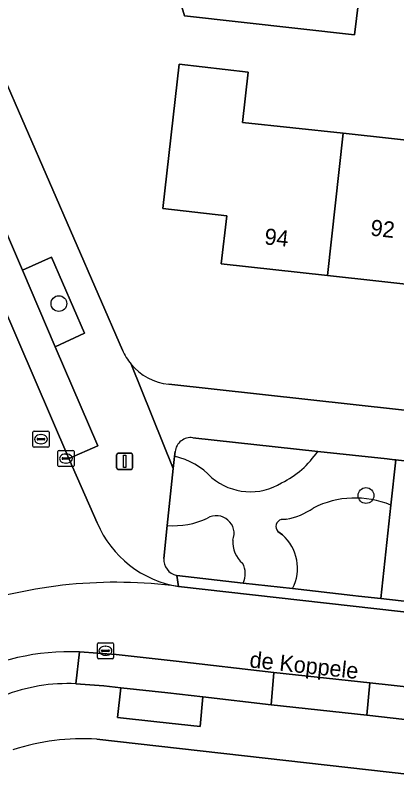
# Model space of a CAD drawing. Extents: x 162026 to 163502, y 387295 to 388169.
# Drawn here: x 162234.69 to 162258.36, y 387817.74 to 387864.8 of the extents above; entities that cross this region are included whole.
import ezdxf

# ---------------------------------------------------------------- set-up
doc = ezdxf.new("R2010")
doc.units = 0
for name, color, linetype in [('IMGEO_Boom', 7, 'Continuous'), ('IMGEO_Erf', 7, 'Continuous'), ('IMGEO_Groenvoorziening', 7, 'Continuous'), ('IMGEO_Kolk', 7, 'Continuous'), ('IMGEO_Lichtmast', 7, 'Continuous'), ('IMGEO_Openbare_ruimte_label', 7, 'Continuous'), ('IMGEO_Pand', 7, 'Continuous'), ('IMGEO_Pand_nummerreeks', 7, 'Continuous'), ('IMGEO_Parkeervlak_open', 7, 'Continuous'), ('IMGEO_Rijbaan_lokaal_open', 7, 'Continuous'), ('IMGEO_Rioolput', 7, 'Continuous'), ('IMGEO_Voetpad_open', 7, 'Continuous')]:
    doc.layers.add(name, color=color, linetype=linetype)

msp = doc.modelspace()

# ---------------------------------------------------------------- linework, layer by layer
at = {"layer": 'IMGEO_Boom'}
for centre in [(162237.406, 387846.934), (162256.452, 387835.043)]:
    msp.add_circle(centre, 0.489, dxfattribs=at)
at = {"layer": 'IMGEO_Erf'}
for points in [[(162281.738, 387867.693), (162271.802, 387868.819), (162271.39, 387865.18), (162268.67, 387865.488), (162266.123, 387865.777), (162266.535, 387869.416), (162259.444, 387870.039), (162259.141, 387866.538), (162256.133, 387866.798), (162255.74, 387863.589), (162245.204, 387864.77), (162244.103, 387868.45), (162232.282, 387864.869), (162241.346, 387844.054)], [(162244.219, 387841.935), (162267.079, 387839.429), (162275.737, 387838.38)], [(162275.948, 387815.9), (162270.899, 387816.432), (162239.75, 387819.947)]]:
    msp.add_lwpolyline(points, dxfattribs=at)
msp.add_lwpolyline([(162261.413, 387856.79), (162267.776, 387856.099), (162274.279, 387855.393), (162273.321, 387846.569), (162266.792, 387847.281), (162260.43, 387847.976), (162254.057, 387848.671), (162247.477, 387849.39), (162247.819, 387852.37), (162243.845, 387852.826), (162244.871, 387861.768), (162249.143, 387861.278), (162248.785, 387858.162), (162255.04, 387857.482)], close=True, dxfattribs=at)
for centre, radius, start, end in [((162244.574, 387845.446), 3.515, 203.329, 220.0767), ((162244.604, 387845.463), 3.549, 219.9769, 263.7763), ((162238.863, 387805.932), 14.043, 86.3776, 107.8507)]:
    msp.add_arc(centre, radius, start, end, dxfattribs=at)
at = {"layer": 'IMGEO_Groenvoorziening'}
for points in [[(162235.158, 387849), (162237.185, 387844.265), (162239.004, 387845.092), (162236.954, 387849.81)], [(162246.34, 387822.571), (162244.161, 387822.82), (162241.24, 387823.141), (162241.046, 387821.3), (162243.475, 387821.028), (162246.158, 387820.737)]]:
    msp.add_lwpolyline(points, close=True, dxfattribs=at)
for points in [[(162253.463, 387837.78), (162245.713, 387838.625)], [(162244.612, 387837.768), (162244.581, 387837.472)], [(162258.294, 387837.248), (162258.229, 387837.256), (162257.77, 387837.31), (162253.463, 387837.78)], [(162244.581, 387837.472), (162244.501, 387836.716), (162244.128, 387833.184)], [(162277.197, 387835.042), (162275.714, 387835.203), (162271.724, 387835.672), (162271.283, 387835.723), (162267.103, 387836.214), (162261.621, 387836.858), (162258.294, 387837.248), (162257.994, 387834.455), (162257.372, 387828.658), (162262.065, 387828.127), (162266.189, 387827.661), (162270.216, 387827.205), (162270.76, 387827.144), (162276.155, 387826.534)], [(162257.994, 387834.455), (162258.294, 387837.248)], [(162251.889, 387829.278), (162255.638, 387828.854), (162255.991, 387828.814), (162257.372, 387828.658), (162257.994, 387834.455)], [(162251.198, 387833.553), (162251.508, 387833.59)], [(162251.508, 387833.59), (162251.198, 387833.553)], [(162244.128, 387833.184), (162243.914, 387831.152)], [(162251.269, 387832.606), (162250.993, 387832.822)], [(162250.993, 387832.822), (162251.269, 387832.606)], [(162244.711, 387830.089), (162248.834, 387829.623)], [(162248.834, 387829.623), (162251.889, 387829.278)]]:
    msp.add_lwpolyline(points, dxfattribs=at)
for centre, radius, start, end in [((162245.586, 387837.652), 0.981, 82.592, 173.2012), ((162248.633, 387841.065), 5.841, 296.3078, 325.7774), ((162248.633, 387841.065), 5.841, 296.3078, 325.7774), ((162243.587, 387833.056), 4.527, 43.1205, 77.315), ((162243.587, 387833.056), 4.527, 43.1205, 77.315), ((162249.278, 387838.98), 3.702, 229.8488, 301.6736), ((162249.278, 387838.98), 3.702, 229.8488, 301.6736), ((162255.79, 387829.102), 5.789, 67.6236, 116.8237), ((162255.79, 387829.102), 5.789, 67.6236, 116.8237), ((162250.942, 387837.38), 3.832, 278.493, 305.7001), ((162250.942, 387837.38), 3.832, 278.493, 305.7001), ((162244.497, 387838.155), 4.985, 265.7548, 295.2067), ((162244.497, 387838.155), 4.985, 265.7548, 295.2067), ((162247.173, 387832.697), 1.098, 338.1023, 120.2524), ((162247.173, 387832.697), 1.098, 338.1023, 120.2524), ((162251.303, 387833.129), 0.437, 103.9662, 224.7028), ((162251.303, 387833.129), 0.437, 103.9662, 224.7028), ((162249.478, 387830.551), 2.726, 332.1718, 48.9345), ((162249.478, 387830.551), 2.726, 332.1718, 48.9345), ((162249.938, 387832.173), 1.75, 176.2733, 229.3442), ((162249.938, 387832.173), 1.75, 176.2733, 229.3442), ((162244.934, 387831.087), 1.022, 176.3263, 257.3963), ((162247.631, 387830.2), 1.334, 334.4001, 28.972), ((162247.631, 387830.2), 1.334, 334.4001, 28.972)]:
    msp.add_arc(centre, radius, start, end, dxfattribs=at)
at = {"layer": 'IMGEO_Kolk'}
for p, q in [((162237.344, 387836.91), (162237.344, 387837.762)), ((162237.419, 387837.836), (162238.271, 387837.836)), ((162238.345, 387837.762), (162238.345, 387836.91)), ((162237.603, 387837.33), (162237.603, 387837.342)), ((162238.041, 387837.293), (162237.643, 387837.293)), ((162237.646, 387837.379), (162238.044, 387837.379)), ((162237.832, 387837.616), (162237.857, 387837.616)), ((162238.087, 387837.342), (162238.087, 387837.33)), ((162238.271, 387836.836), (162237.419, 387836.836)), ((162237.855, 387837.056), (162237.83, 387837.056)), ((162239.867, 387825.929), (162240.719, 387825.929)), ((162239.792, 387825.003), (162239.792, 387825.855)), ((162240.051, 387825.423), (162240.051, 387825.435)), ((162240.094, 387825.472), (162240.492, 387825.472)), ((162240.28, 387825.709), (162240.305, 387825.709)), ((162240.535, 387825.435), (162240.535, 387825.423)), ((162240.793, 387825.855), (162240.793, 387825.003)), ((162240.489, 387825.386), (162240.091, 387825.386)), ((162240.303, 387825.149), (162240.278, 387825.149)), ((162240.719, 387824.929), (162239.867, 387824.929))]:
    msp.add_line(p, q, dxfattribs=at)
for points in [[(162237.344, 387836.91), (162237.344, 387837.762)], [(162237.419, 387837.836), (162238.271, 387837.836)], [(162238.345, 387837.762), (162238.345, 387836.91)], [(162238.271, 387836.836), (162237.419, 387836.836)], [(162239.867, 387825.929), (162240.719, 387825.929)], [(162239.792, 387825.003), (162239.792, 387825.855)], [(162240.793, 387825.855), (162240.793, 387825.003)], [(162240.719, 387824.929), (162239.867, 387824.929)]]:
    msp.add_lwpolyline(points, dxfattribs=at)
for centre, radius, start, end in [((162237.421, 387837.76), 0.0765, 91.552, 178.448), ((162237.421, 387837.76), 0.0765, 91.552, 178.448), ((162238.269, 387837.76), 0.0765, 1.552, 88.448), ((162238.269, 387837.76), 0.0765, 1.552, 88.448), ((162237.643, 387837.339), 0.0403, 85.8775, 175.7526), ((162237.64, 387837.329), 0.0366, 178.938, 274.7102), ((162238.044, 387837.336), 0.043, 264.8664, 352.4533), ((162238.048, 387837.341), 0.0386, 1.7309, 96.639), ((162237.421, 387836.912), 0.0765, 181.552, 268.448), ((162237.421, 387836.912), 0.0765, 181.552, 268.448), ((162238.269, 387836.912), 0.0765, 271.552, 358.448), ((162238.269, 387836.912), 0.0765, 271.552, 358.448), ((162239.869, 387825.853), 0.0765, 91.552, 178.448), ((162239.869, 387825.853), 0.0765, 91.552, 178.448), ((162240.717, 387825.853), 0.0765, 1.552, 88.448), ((162240.717, 387825.853), 0.0765, 1.552, 88.448), ((162240.091, 387825.432), 0.0403, 85.8775, 175.7526), ((162240.088, 387825.422), 0.0366, 178.938, 274.7102), ((162240.492, 387825.429), 0.043, 264.8664, 352.4533), ((162240.496, 387825.434), 0.0386, 1.7309, 96.639), ((162239.869, 387825.005), 0.0765, 181.552, 268.448), ((162239.869, 387825.005), 0.0765, 181.552, 268.448), ((162240.717, 387825.005), 0.0765, 271.552, 358.448), ((162240.717, 387825.005), 0.0765, 271.552, 358.448)]:
    msp.add_arc(centre, radius, start, end, dxfattribs=at)
for centre, major_axis, ratio, start_param, end_param in [((162237.831, 387837.336), (-0.387, 0.002), 0.722429, 4.712389, 7.853982), ((162237.856, 387837.336), (-0.39, 0.002), 0.717154, 1.570796, 4.712389), ((162240.279, 387825.429), (-0.387, 0.002), 0.722429, 4.712389, 7.853982), ((162240.304, 387825.429), (-0.39, 0.002), 0.717154, 1.570796, 4.712389)]:
    msp.add_ellipse(centre, major_axis=major_axis, ratio=ratio, start_param=start_param, end_param=end_param, dxfattribs=at)
at = {"layer": 'IMGEO_Lichtmast'}
for p, q in [((162241.089, 387837.665), (162241.879, 387837.665)), ((162241.879, 387837.665), (162241.089, 387837.665)), ((162240.989, 387836.765), (162240.989, 387837.565)), ((162240.989, 387837.565), (162240.989, 387836.765)), ((162241.979, 387837.565), (162241.979, 387836.765)), ((162241.979, 387836.765), (162241.979, 387837.565)), ((162241.879, 387836.665), (162241.089, 387836.665)), ((162241.089, 387836.665), (162241.879, 387836.665))]:
    msp.add_line(p, q, dxfattribs=at)
msp.add_lwpolyline([(162241.409, 387837.54), (162241.559, 387837.54), (162241.559, 387836.79), (162241.409, 387836.79), (162241.409, 387837.54)], dxfattribs=at)
for centre, start, end in [((162241.089, 387837.565), 90, 180), ((162241.089, 387837.565), 90, 180), ((162241.879, 387837.565), 0, 90), ((162241.879, 387837.565), 360, 90), ((162241.089, 387836.765), 180, 270), ((162241.089, 387836.765), 180, 270), ((162241.879, 387836.765), 270, 0), ((162241.879, 387836.765), 270, 0)]:
    msp.add_arc(centre, 0.1, start, end, dxfattribs=at)
at = {"layer": 'IMGEO_Pand'}
for points in [[(162256.567, 387870.335), (162252.068, 387870.87), (162244.103, 387868.45), (162245.204, 387864.77), (162255.74, 387863.589), (162256.133, 387866.798)], [(162255.04, 387857.482), (162248.785, 387858.162), (162249.143, 387861.278), (162244.871, 387861.768), (162243.845, 387852.826), (162247.819, 387852.37), (162247.477, 387849.39), (162254.057, 387848.671)], [(162255.04, 387857.482), (162254.057, 387848.671), (162260.43, 387847.976), (162261.413, 387856.79)]]:
    msp.add_lwpolyline(points, close=True, dxfattribs=at)
at = {"layer": 'IMGEO_Parkeervlak_open'}
for points in [[(162231.569, 387857.298), (162230.255, 387860.338), (162228.452, 387859.53), (162238.031, 387837.33), (162239.821, 387838.129), (162237.185, 387844.265), (162235.158, 387849)], [(162250.744, 387824.091), (162244.673, 387824.775), (162240.948, 387825.201), (162238.679, 387825.353), (162238.465, 387823.383), (162240.196, 387823.256), (162241.24, 387823.141), (162244.161, 387822.82), (162246.34, 387822.571), (162250.562, 387822.082)]]:
    msp.add_lwpolyline(points, close=True, dxfattribs=at)
for points in [[(162256.693, 387823.44), (162256.504, 387821.431), (162261.027, 387820.917), (162264.182, 387820.559)], [(162265.928, 387820.159), (162267.143, 387819.94), (162268.136, 387819.735), (162268.392, 387822.16), (162256.693, 387823.44)]]:
    msp.add_lwpolyline(points, dxfattribs=at)
at = {"layer": 'IMGEO_Rijbaan_lokaal_open'}
for points in [[(162239.78, 387833.354), (162238.031, 387837.33), (162228.452, 387859.53)], [(162238.679, 387825.353), (162240.948, 387825.201), (162244.673, 387824.775), (162250.744, 387824.091), (162256.693, 387823.44), (162268.392, 387822.16), (162268.878, 387826.764), (162267.769, 387826.833), (162244.818, 387829.41)], [(162238.465, 387823.383), (162238.679, 387825.353)]]:
    msp.add_lwpolyline(points, dxfattribs=at)
msp.add_lwpolyline([(162256.693, 387823.44), (162250.744, 387824.091), (162250.562, 387822.082), (162256.504, 387821.431)], close=True, dxfattribs=at)
for centre, radius, start, end in [((162245.852, 387835.92), 6.592, 202.9123, 260.9764), ((162240.931, 387800.369), 29.3, 82.3772, 108.9015), ((162240.931, 387800.369), 29.3, 82.3772, 108.9015), ((162238.041, 387811.147), 14.22, 87.4293, 118.5678), ((162238.041, 387811.147), 14.22, 87.4293, 118.5678), ((162237.945, 387812.649), 10.746, 87.2287, 111.6711)]:
    msp.add_arc(centre, radius, start, end, dxfattribs=at)
at = {"layer": 'IMGEO_Rioolput'}
for p, q in [((162235.793, 387838.11), (162235.793, 387838.962)), ((162235.868, 387839.036), (162236.72, 387839.036)), ((162236.095, 387838.579), (162236.493, 387838.579)), ((162236.281, 387838.816), (162236.306, 387838.816)), ((162236.794, 387838.962), (162236.794, 387838.11)), ((162236.052, 387838.53), (162236.052, 387838.542)), ((162236.49, 387838.493), (162236.092, 387838.493)), ((162236.304, 387838.256), (162236.279, 387838.256)), ((162236.536, 387838.542), (162236.536, 387838.53)), ((162236.72, 387838.036), (162235.868, 387838.036))]:
    msp.add_line(p, q, dxfattribs=at)
for points in [[(162235.793, 387838.11), (162235.793, 387838.962)], [(162235.868, 387839.036), (162236.72, 387839.036)], [(162236.794, 387838.962), (162236.794, 387838.11)], [(162236.72, 387838.036), (162235.868, 387838.036)]]:
    msp.add_lwpolyline(points, dxfattribs=at)
for centre, radius, start, end in [((162235.87, 387838.96), 0.0765, 91.552, 178.448), ((162235.87, 387838.96), 0.0765, 91.552, 178.448), ((162236.092, 387838.539), 0.0403, 85.8775, 175.7526), ((162236.497, 387838.541), 0.0386, 1.7309, 96.639), ((162236.718, 387838.96), 0.0765, 1.552, 88.448), ((162236.718, 387838.96), 0.0765, 1.552, 88.448), ((162235.87, 387838.112), 0.0765, 181.552, 268.448), ((162235.87, 387838.112), 0.0765, 181.552, 268.448), ((162236.089, 387838.529), 0.0366, 178.938, 274.7102), ((162236.493, 387838.536), 0.043, 264.8664, 352.4533), ((162236.718, 387838.112), 0.0765, 271.552, 358.448), ((162236.718, 387838.112), 0.0765, 271.552, 358.448)]:
    msp.add_arc(centre, radius, start, end, dxfattribs=at)
for centre, major_axis, ratio, start_param, end_param in [((162236.28, 387838.536), (-0.387, 0.002), 0.722429, 4.712389, 7.853982), ((162236.305, 387838.536), (-0.39, 0.002), 0.717154, 1.570796, 4.712389)]:
    msp.add_ellipse(centre, major_axis=major_axis, ratio=ratio, start_param=start_param, end_param=end_param, dxfattribs=at)
at = {"layer": 'IMGEO_Voetpad_open'}
for points in [[(162241.346, 387844.054), (162232.282, 387864.869), (162231.603, 387866.429), (162205.445, 387926.498)], [(162226.899, 387868.081), (162230.255, 387860.338), (162232.072, 387861.151), (162233.378, 387858.093), (162231.569, 387857.298), (162235.158, 387849), (162236.954, 387849.81), (162239.004, 387845.092), (162237.185, 387844.265), (162239.821, 387838.129), (162238.031, 387837.33), (162239.78, 387833.354)], [(162243.914, 387831.152), (162244.128, 387833.184), (162244.501, 387836.716), (162241.884, 387843.183)], [(162241.884, 387843.183), (162244.501, 387836.716), (162244.581, 387837.472), (162244.612, 387837.768)], [(162275.737, 387838.38), (162267.079, 387839.429), (162244.219, 387841.935)], [(162245.713, 387838.625), (162253.463, 387837.78), (162257.77, 387837.31), (162258.229, 387837.256), (162258.294, 387837.248), (162261.621, 387836.858), (162267.103, 387836.214), (162271.283, 387835.723), (162271.724, 387835.672), (162275.714, 387835.203), (162277.197, 387835.042)], [(162244.818, 387829.41), (162244.711, 387830.089)], [(162262.065, 387828.127), (162257.372, 387828.658), (162255.991, 387828.814), (162255.638, 387828.854), (162251.889, 387829.278), (162248.834, 387829.623), (162244.711, 387830.089), (162244.818, 387829.41), (162267.769, 387826.833), (162268.878, 387826.764), (162269.901, 387826.66), (162277.144, 387825.832), (162277.255, 387827.421)], [(162241.24, 387823.141), (162240.196, 387823.256), (162238.465, 387823.383)], [(162239.75, 387819.947), (162270.899, 387816.432), (162275.948, 387815.9), (162276.387, 387818.853), (162271.485, 387819.369), (162269.281, 387819.617), (162268.136, 387819.735), (162267.143, 387819.94), (162265.928, 387820.159), (162265.748, 387818.453), (162260.783, 387819.067), (162261.027, 387820.917), (162256.504, 387821.431), (162250.562, 387822.082), (162246.34, 387822.571), (162246.158, 387820.737), (162243.475, 387821.028), (162241.046, 387821.3), (162241.24, 387823.141)]]:
    msp.add_lwpolyline(points, dxfattribs=at)
for centre, radius, start, end in [((162244.574, 387845.446), 3.515, 203.329, 220.0767), ((162244.604, 387845.463), 3.549, 219.9769, 263.7763), ((162245.586, 387837.652), 0.981, 82.592, 173.2012), ((162245.852, 387835.92), 6.592, 202.9123, 260.9764), ((162244.934, 387831.087), 1.022, 176.3263, 257.3963), ((162237.945, 387812.649), 10.746, 87.2287, 111.6711), ((162238.863, 387805.932), 14.043, 86.3776, 107.8507)]:
    msp.add_arc(centre, radius, start, end, dxfattribs=at)

# ---------------------------------------------------------------- texts
at = {"layer": 'IMGEO_Openbare_ruimte_label'}
msp.add_text('de Koppele', height=1, rotation=353.856, dxfattribs=at).set_placement((162249.197, 387824.401))
at = {"layer": 'IMGEO_Pand_nummerreeks'}
for s, rotation, p in [('92', 353.6422, (162256.696, 387851.155)), ('94', 353.764, (162250.119, 387850.61))]:
    msp.add_text(s, height=1, rotation=rotation, dxfattribs=at).set_placement(p)

doc.saveas('drawing.dxf')
